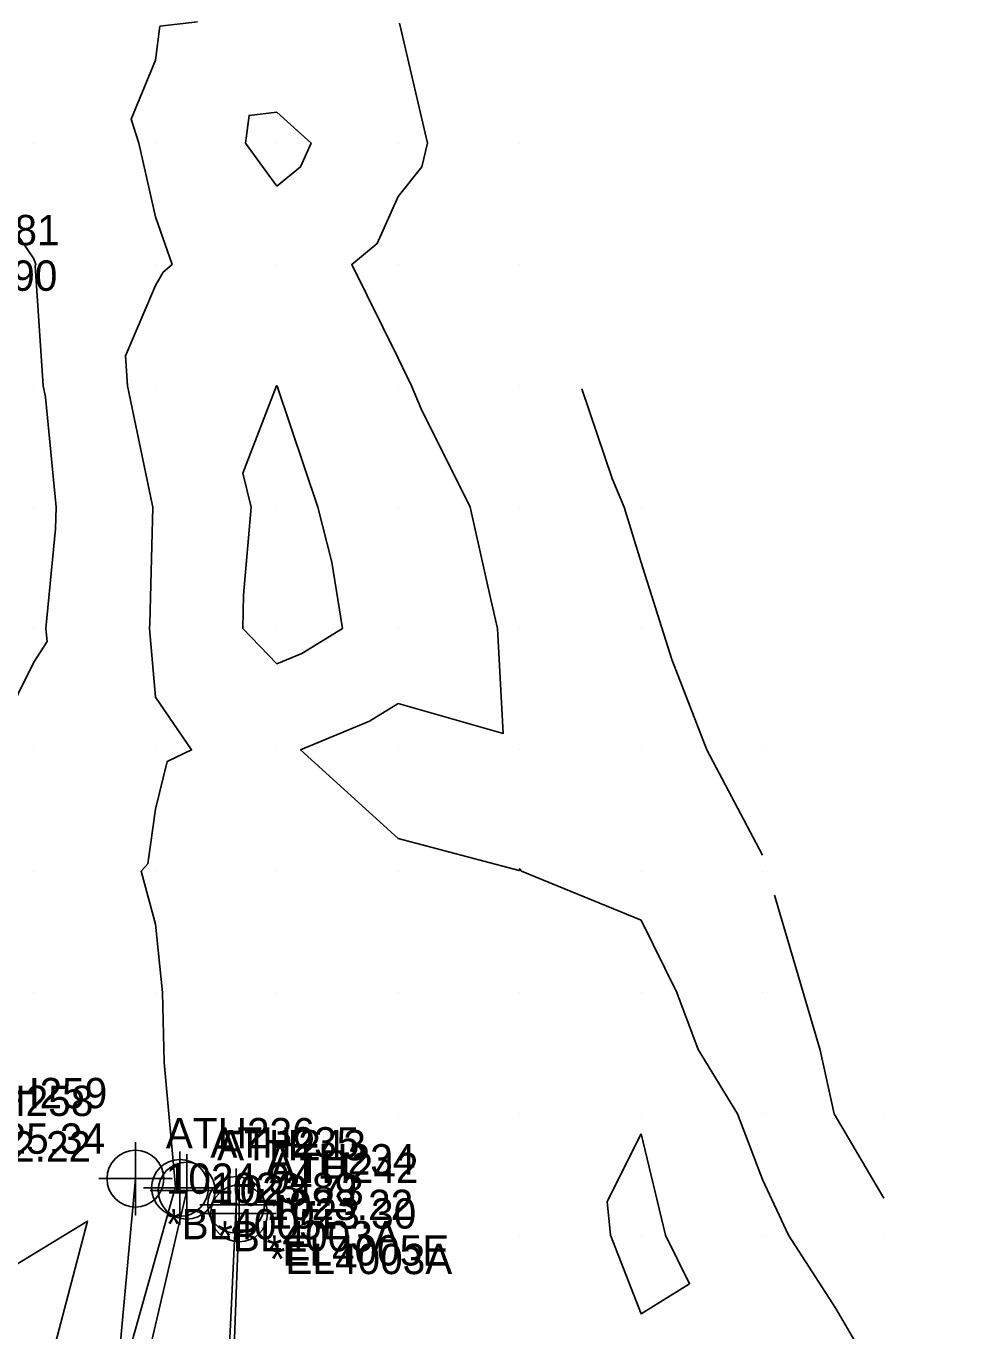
# Model space of a CAD drawing. Extents: x 1213164 to 1213550, y 766120 to 766870.
# Drawn here: x 1213449.4 to 1213527.4, y 766292.1 to 766399.6 of the extents above; entities that cross this region are included whole.
import ezdxf

# ---------------------------------------------------------------- set-up
doc = ezdxf.new("R2010")
doc.units = 0
for name, color, linetype in [('Default', 7, 'Continuous'), ('Exist DTM Breakline', 7, 'Continuous'), ('Exist DTM Breakline Cogo Comment', 7, 'Continuous'), ('Exist DTM Breakline Cogo Elevation', 7, 'Continuous'), ('Exist DTM Breakline Cogo Number', 7, 'Continuous'), ('Exist DTM Breakline Cogo Point CELL', 7, 'Continuous'), ('Exist DTM Drainline Cogo Comment', 7, 'Continuous'), ('Exist DTM Drainline Cogo Elevation', 7, 'Continuous'), ('Exist DTM Drainline Cogo Number', 7, 'Continuous'), ('Exist DTM Drainline Cogo Point CELL', 7, 'Continuous'), ('Exist DTM QL2 LIDAR Elevation Point', 7, 'Continuous'), ('Exist DTM Regular Point Cogo Elevation', 7, 'Continuous'), ('Exist DTM Regular Point Cogo Number', 7, 'Continuous'), ('Exist DTM Regular Point Underwater CELL', 7, 'Continuous'), ('Exist DTM Regular Point Underwater Cogo Elevation', 7, 'Continuous'), ('Exist DTM Regular Point Underwater Cogo Number', 7, 'Continuous'), ('Exist Hydro Stream or Body of Water', 7, 'Continuous')]:
    doc.layers.add(name, color=color, linetype=linetype)

msp = doc.modelspace()

# ---------------------------------------------------------------- linework, layer by layer
at = {"layer": 'Default'}
for points in [[(1213457.67, 766289.82), (1213461.64, 766303.9), (1213461.66, 766303.99), (1213460.73, 766314.24), (1213460.58, 766320), (1213460, 766325.64), (1213458.82, 766330), (1213459.38, 766330.62), (1213460, 766335.11), (1213460.96, 766339.04), (1213462.99, 766340), (1213460, 766344.33), (1213459.51, 766350), (1213459.55, 766350.45), (1213459.78, 766360), (1213459.75, 766360.25), (1213457.7, 766370), (1213457.54, 766372.46), (1213460, 766378.26), (1213460.65, 766379.35), (1213461.38, 766380), (1213460, 766383.92), (1213458.63, 766390), (1213458.02, 766391.98), (1213460, 766396.83), (1213460.37, 766399.63), (1213463.48, 766400)], [(1213480.11, 766399.89), (1213482.42, 766390), (1213481.95, 766388.05), (1213480, 766385.59), (1213478.28, 766381.72), (1213476.17, 766380), (1213480, 766372.27), (1213481.09, 766370), (1213481.9, 766368.1), (1213485.92, 766360), (1213487.62, 766352.38), (1213488.18, 766350), (1213488.65, 766341.35), (1213480, 766343.81), (1213477.63, 766342.37), (1213471.96, 766340), (1213480, 766332.7), (1213489.95, 766330.05), (1213490, 766330.2), (1213490.15, 766330), (1213500, 766325.97), (1213502.93, 766320), (1213504.7, 766315.3), (1213507.95, 766310), (1213510, 766304.6), (1213512.15, 766300), (1213516.04, 766293.96), (1213518.35, 766290)], [(1213470, 766386.44), (1213467.42, 766390), (1213467.72, 766392.28), (1213470, 766392.55), (1213472.83, 766390), (1213471.96, 766388.04), (1213470, 766386.44)], [(1213443.49, 766390), (1213450, 766380.45), (1213450.16, 766380), (1213450.11, 766379.89), (1213450.75, 766370), (1213450.95, 766369.05), (1213451.83, 766360), (1213451.79, 766358.21), (1213450.98, 766350), (1213451.08, 766348.92), (1213450, 766347.23), (1213446.05, 766339.28)], [(1213475.41, 766350), (1213474.54, 766355.46), (1213473.37, 766360), (1213470.03, 766369.97), (1213470.01, 766370), (1213470, 766370.02), (1213469.99, 766370.01), (1213469.98, 766370), (1213467.21, 766362.79), (1213467.9, 766360), (1213467.26, 766352.74), (1213467.2, 766350), (1213470, 766347.1), (1213472.05, 766347.95), (1213475.41, 766350)], [(1213495.13, 766369.75), (1213497.63, 766362.37), (1213498.6, 766360), (1213500, 766355.44), (1213502.54, 766347.46), (1213505.42, 766340), (1213510, 766331.32)], [(1213510.99, 766328.02), (1213514.75, 766315.25), (1213515.91, 766310), (1213520, 766303.07)], [(1213500, 766308.35), (1213497.21, 766302.79), (1213497.48, 766300), (1213500, 766293.54), (1213503.99, 766296.01), (1213502, 766300), (1213500, 766308.35)], [(1213444.83, 766295.35), (1213454.41, 766301.17), (1213450.33, 766285.56)]]:
    msp.add_lwpolyline(points, dxfattribs=at)
at = {"layer": 'Exist DTM Breakline'}
for points in [[(1213458.36, 766304.67), (1213456.15, 766280.48), (1213457.95, 766246.9), (1213447.47, 766261.8), (1213441.28, 766307.97), (1213433.95, 766370.73), (1213403.81, 766386.39), (1213393.08, 766404.94), (1213391.08, 766440.45), (1213383.54, 766456.52), (1213369.39, 766482.2), (1213351.86, 766502.12)], [(1213527.41, 766246.33), (1213487.24, 766246.78), (1213487.06, 766248.33), (1213465.46, 766241.67), (1213466.02, 766278.27), (1213466.9, 766301.8)]]:
    msp.add_lwpolyline(points, dxfattribs=at)
at = {"layer": 'Exist DTM Breakline Cogo Point CELL'}
for points in [[(1213458.36, 766307.67), (1213458.36, 766301.67), (1213458.36, 766304.67), (1213461.36, 766304.67), (1213455.36, 766304.67)], [(1213466.65, 766305.51), (1213466.65, 766299.51), (1213466.65, 766302.51), (1213469.65, 766302.51), (1213463.65, 766302.51)]]:
    msp.add_lwpolyline(points, dxfattribs=at)
for centre in [(1213458.36, 766304.67), (1213466.65, 766302.51)]:
    msp.add_circle(centre, 2.34, dxfattribs=at)
at = {"layer": 'Exist DTM Drainline Cogo Point CELL'}
for points in [[(1213462.58, 766306.68), (1213462.58, 766300.68), (1213462.58, 766303.68), (1213465.58, 766303.68), (1213459.58, 766303.68)], [(1213466.9, 766304.8), (1213466.9, 766298.8), (1213466.9, 766301.8), (1213469.9, 766301.8), (1213463.9, 766301.8)]]:
    msp.add_lwpolyline(points, dxfattribs=at)
for centre in [(1213462.58, 766303.68), (1213466.9, 766301.8)]:
    msp.add_circle(centre, 2.34, dxfattribs=at)
at = {"layer": 'Exist DTM QL2 LIDAR Elevation Point'}
for p, q in [((1213450, 766390), (1213450, 766390)), ((1213460, 766390), (1213460, 766390)), ((1213470, 766390), (1213470, 766390)), ((1213480, 766390), (1213480, 766390)), ((1213490, 766390), (1213490, 766390)), ((1213450, 766380), (1213450, 766380)), ((1213460, 766380), (1213460, 766380)), ((1213470, 766380), (1213470, 766380)), ((1213480, 766380), (1213480, 766380)), ((1213490, 766380), (1213490, 766380)), ((1213450, 766370), (1213450, 766370)), ((1213460, 766370), (1213460, 766370)), ((1213470, 766370), (1213470, 766370)), ((1213480, 766370), (1213480, 766370)), ((1213490, 766370), (1213490, 766370)), ((1213450, 766360), (1213450, 766360)), ((1213460, 766360), (1213460, 766360)), ((1213470, 766360), (1213470, 766360)), ((1213480, 766360), (1213480, 766360)), ((1213490, 766360), (1213490, 766360)), ((1213500, 766360), (1213500, 766360)), ((1213450, 766350), (1213450, 766350)), ((1213460, 766350), (1213460, 766350)), ((1213470, 766350), (1213470, 766350)), ((1213480, 766350), (1213480, 766350)), ((1213490, 766350), (1213490, 766350)), ((1213500, 766350), (1213500, 766350)), ((1213450, 766340), (1213450, 766340)), ((1213460, 766340), (1213460, 766340)), ((1213470, 766340), (1213470, 766340)), ((1213480, 766340), (1213480, 766340)), ((1213490, 766340), (1213490, 766340)), ((1213500, 766340), (1213500, 766340)), ((1213510, 766340), (1213510, 766340)), ((1213450, 766330), (1213450, 766330)), ((1213460, 766330), (1213460, 766330)), ((1213470, 766330), (1213470, 766330)), ((1213480, 766330), (1213480, 766330)), ((1213490, 766330), (1213490, 766330)), ((1213500, 766330), (1213500, 766330)), ((1213510, 766330), (1213510, 766330)), ((1213450, 766320), (1213450, 766320)), ((1213460, 766320), (1213460, 766320)), ((1213470, 766320), (1213470, 766320)), ((1213480, 766320), (1213480, 766320)), ((1213490, 766320), (1213490, 766320)), ((1213500, 766320), (1213500, 766320)), ((1213510, 766320), (1213510, 766320)), ((1213450, 766310), (1213450, 766310)), ((1213480, 766310), (1213480, 766310)), ((1213490, 766310), (1213490, 766310)), ((1213500, 766310), (1213500, 766310)), ((1213510, 766310), (1213510, 766310)), ((1213520, 766310), (1213520, 766310)), ((1213480, 766300), (1213480, 766300)), ((1213490, 766300), (1213490, 766300)), ((1213500, 766300), (1213500, 766300)), ((1213510, 766300), (1213510, 766300)), ((1213520, 766300), (1213520, 766300))]:
    msp.add_line(p, q, dxfattribs=at)
at = {"layer": 'Exist DTM Regular Point Underwater CELL'}
msp.add_lwpolyline([(1213462.03, 766306.91), (1213462.03, 766300.91), (1213462.03, 766303.91), (1213465.03, 766303.91), (1213459.03, 766303.91)], dxfattribs=at)
msp.add_circle((1213462.03, 766303.91), 2.34, dxfattribs=at)
at = {"layer": 'Exist Hydro Stream or Body of Water'}
for points in [[(1213462.58, 766303.68), (1213457.24, 766280.72), (1213458.54, 766244.27), (1213446.98, 766261.33), (1213440.13, 766307.33), (1213429.65, 766367.83), (1213400.18, 766384.29), (1213389.88, 766405.51), (1213387.13, 766439.71), (1213382.82, 766456.43), (1213368.02, 766480.63), (1213349.52, 766498.12), (1213324.24, 766505.78)], [(1213526.67, 766245), (1213464.88, 766240.54), (1213465.59, 766279.89), (1213466.65, 766302.51)]]:
    msp.add_lwpolyline(points, dxfattribs=at)

# ---------------------------------------------------------------- texts
at = {"layer": 'Exist DTM Breakline Cogo Comment'}
for s, p in [('*BL4005E', (1213460.86, 766299.67)), ('*EL4005E', (1213469.15, 766297.51))]:
    msp.add_text(s, height=2.5, dxfattribs=at).set_placement(p)
at = {"layer": 'Exist DTM Breakline Cogo Elevation'}
for s, p in [('1025.34', (1213443.78, 766306.72)), ('1024.94', (1213460.86, 766303.42)), ('1023.22', (1213469.15, 766301.26))]:
    msp.add_text(s, height=2.5, dxfattribs=at).set_placement(p)
at = {"layer": 'Exist DTM Breakline Cogo Number'}
for s, p in [('ATH259', (1213443.78, 766310.47)), ('ATH236', (1213460.86, 766307.17)), ('ATH234', (1213469.15, 766305.01))]:
    msp.add_text(s, height=2.5, dxfattribs=at).set_placement(p)
at = {"layer": 'Exist DTM Drainline Cogo Comment'}
for s, p in [('*BL4003A', (1213465.08, 766298.68)), ('*EL4003A', (1213469.4, 766296.8))]:
    msp.add_text(s, height=2.5, dxfattribs=at).set_placement(p)
at = {"layer": 'Exist DTM Drainline Cogo Elevation'}
for s, p in [('1022.22', (1213442.63, 766306.08)), ('1023.73', (1213465.08, 766302.43)), ('1023.30', (1213469.4, 766300.55))]:
    msp.add_text(s, height=2.5, dxfattribs=at).set_placement(p)
at = {"layer": 'Exist DTM Drainline Cogo Number'}
for s, p in [('ATH258', (1213442.63, 766309.83)), ('ATH243', (1213465.08, 766306.18)), ('ATH242', (1213469.4, 766304.3))]:
    msp.add_text(s, height=2.5, dxfattribs=at).set_placement(p)
at = {"layer": 'Exist DTM Regular Point Cogo Elevation'}
msp.add_text('1025.90', height=2.5, dxfattribs=at).set_placement((1213439.85, 766377.83))
at = {"layer": 'Exist DTM Regular Point Cogo Number'}
msp.add_text('ATH281', height=2.5, dxfattribs=at).set_placement((1213439.85, 766381.58))
at = {"layer": 'Exist DTM Regular Point Underwater Cogo Elevation'}
msp.add_text('1023.89', height=2.5, dxfattribs=at).set_placement((1213464.53, 766302.66))
at = {"layer": 'Exist DTM Regular Point Underwater Cogo Number'}
msp.add_text('ATH235', height=2.5, dxfattribs=at).set_placement((1213464.53, 766306.41))

doc.saveas('drawing.dxf')
